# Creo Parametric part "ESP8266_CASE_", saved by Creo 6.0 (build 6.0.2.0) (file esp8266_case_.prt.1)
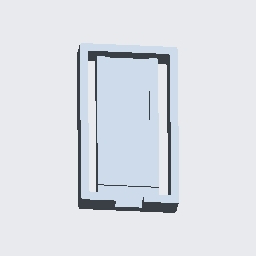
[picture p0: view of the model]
Units: Inch lbm Second (Pro/E Default); INCH, POUND, SECS

Created from: INLBS_PART_SOLID.PRT

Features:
  1. datum plane "RIGHT"
  2. datum plane "TOP"
  3. datum plane "FRONT"
  4. coordinate system
  5. sketch "Sketch 1"
  6. extrusion "Extrude 1"
  7. sketch "Sketch 2"
  8. extrusion "Extrude 2"
  9. sketch "Sketch 3"
  10. extruded cut "Extrude 3"
  11. sketch "Sketch 4"
  12. extruded cut "Extrude 4"
  13. sketch "Sketch 5"
  14. extruded cut "Extrude 5"
  15. round "Round 1"

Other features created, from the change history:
  sketch "Sketch 4"
  extruded cut "Extrude 4"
